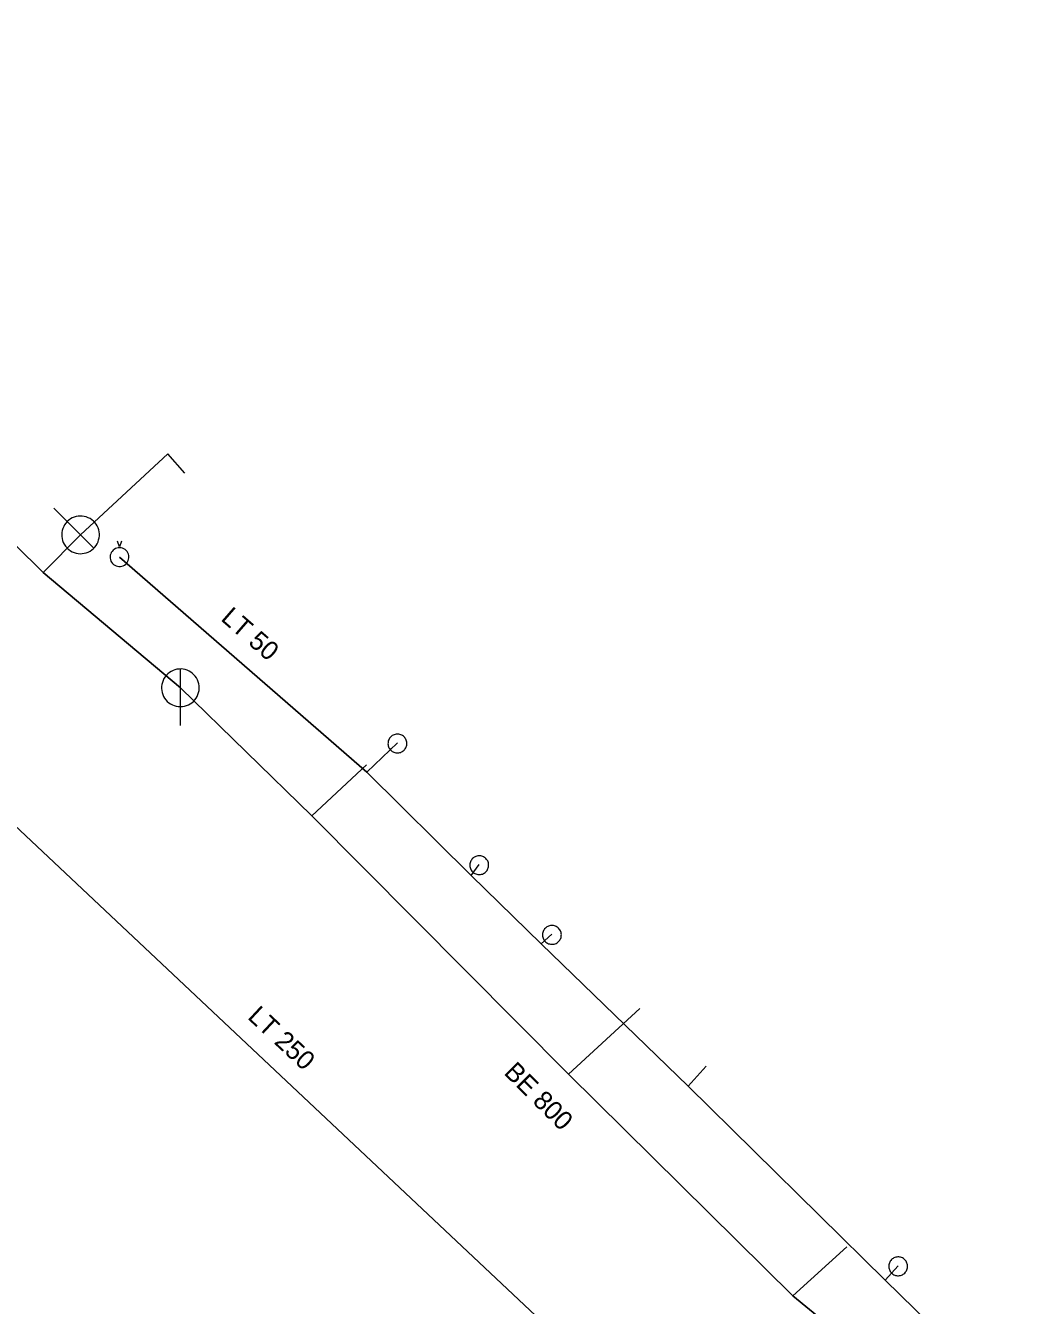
# Model space of a CAD drawing. Extents: x -807203 to -805207, y -993656 to -992505.
# Drawn here: x -806024 to -805970.4, y -993281.2 to -993213.2 of the extents above; entities that cross this region are included whole.
import ezdxf

# ---------------------------------------------------------------- set-up
doc = ezdxf.new("R2010")
doc.units = 0
doc.header["$LTSCALE"] = 0.4
for name, color, linetype, lineweight in [('1', 7, 'Continuous', 13), ('11', 7, 'Continuous', 13), ('13', 7, 'Continuous', 13), ('14', 7, 'Continuous', 25), ('17', 7, 'Continuous', 25), ('22', 7, 'Continuous', 13), ('23', 7, 'Continuous', 13)]:
    doc.layers.add(name, color=color, linetype=linetype, lineweight=lineweight)

msp = doc.modelspace()

# ---------------------------------------------------------------- linework, layer by layer
at = {"layer": '11'}
for p, q in [((-806021.12, -993240.27), (-806023.109, -993242.259)), ((-806005.943, -993252.482), (-806008.844, -993255.179)), ((-805991.421, -993265.414), (-805995.221, -993268.897)), ((-805980.442, -993278.079), (-805983.297, -993280.672))]:
    msp.add_line(p, q, dxfattribs=at)
msp.add_lwpolyline([(-806015.584, -993236.985), (-806016.482, -993235.959), (-806021.12, -993240.27)], dxfattribs=at)
at = {"layer": '13'}
for p, q in [((-806005.914, -993252.87), (-806004.298, -993251.316)), ((-806000.375, -993258.351), (-805999.953, -993257.777)), ((-805996.668, -993261.975), (-805996.094, -993261.478)), ((-805988.86, -993269.541), (-805987.907, -993268.484)), ((-805978.403, -993279.84), (-805977.714, -993279.075))]:
    msp.add_line(p, q, dxfattribs=at)
at = {"layer": '14'}
for points in [[(-806052.51, -993213.23), (-806023.109, -993242.259), (-806015.82, -993248.39)], [(-806015.82, -993248.39), (-806008.844, -993255.179), (-805995.221, -993268.897), (-805983.297, -993280.672), (-805980.85, -993282.69)]]:
    msp.add_lwpolyline(points, dxfattribs=at)
at = {"layer": '17'}
for points in [[(-805970.428, -993287.685), (-805972.109, -993286.008), (-805978.403, -993279.84), (-805988.86, -993269.541), (-805996.668, -993261.975), (-806000.375, -993258.351), (-806005.914, -993252.87), (-806019.053, -993241.45)], [(-805980.27, -993297.811), (-805996.344, -993282.298), (-806025.237, -993255.101)]]:
    msp.add_lwpolyline(points, dxfattribs=at)
at = {"layer": '22'}
for p, q in [((-806022.534, -993238.855), (-806020.413, -993240.976)), ((-806015.82, -993250.39), (-806015.819, -993247.39))]:
    msp.add_line(p, q, dxfattribs=at)
for points in [[(-806021.827, -993240.976), (-806021.746, -993241.049), (-806021.657, -993241.113), (-806021.561, -993241.166), (-806021.461, -993241.21), (-806021.356, -993241.241), (-806021.248, -993241.261), (-806021.138, -993241.269), (-806021.03, -993241.265), (-806020.921, -993241.249), (-806020.815, -993241.222), (-806020.713, -993241.183), (-806020.615, -993241.132), (-806020.524, -993241.072), (-806020.44, -993241.002), (-806020.363, -993240.923), (-806020.297, -993240.836), (-806020.239, -993240.743), (-806020.192, -993240.644), (-806020.158, -993240.54), (-806020.133, -993240.434), (-806020.121, -993240.325), (-806020.121, -993240.216), (-806020.133, -993240.106), (-806020.157, -993239.999), (-806020.192, -993239.896), (-806020.239, -993239.797), (-806020.296, -993239.703), (-806020.362, -993239.617), (-806020.439, -993239.537), (-806020.523, -993239.467), (-806020.613, -993239.407), (-806020.711, -993239.357), (-806020.813, -993239.317), (-806020.919, -993239.289), (-806021.028, -993239.274), (-806021.137, -993239.269), (-806021.246, -993239.277), (-806021.354, -993239.297), (-806021.458, -993239.328), (-806021.559, -993239.371), (-806021.655, -993239.424), (-806021.744, -993239.488), (-806021.826, -993239.561), (-806021.899, -993239.642), (-806021.963, -993239.732), (-806022.016, -993239.826), (-806022.06, -993239.927), (-806022.091, -993240.033), (-806022.111, -993240.14), (-806022.12, -993240.249), (-806022.116, -993240.359), (-806022.1, -993240.467), (-806022.073, -993240.573), (-806022.034, -993240.675), (-806021.984, -993240.772), (-806021.923, -993240.864), (-806021.853, -993240.948)], [(-806014.82, -993248.39), (-806014.825, -993248.281), (-806014.843, -993248.173), (-806014.873, -993248.067), (-806014.913, -993247.966), (-806014.965, -993247.869), (-806015.027, -993247.779), (-806015.099, -993247.696), (-806015.179, -993247.622), (-806015.267, -993247.556), (-806015.361, -993247.501), (-806015.461, -993247.456), (-806015.566, -993247.423), (-806015.673, -993247.401), (-806015.782, -993247.391), (-806015.892, -993247.393), (-806016, -993247.407), (-806016.107, -993247.432), (-806016.21, -993247.469), (-806016.308, -993247.518), (-806016.4, -993247.576), (-806016.486, -993247.645), (-806016.563, -993247.722), (-806016.632, -993247.808), (-806016.691, -993247.9), (-806016.739, -993247.998), (-806016.776, -993248.101), (-806016.802, -993248.208), (-806016.816, -993248.316), (-806016.819, -993248.426), (-806016.809, -993248.535), (-806016.788, -993248.642), (-806016.754, -993248.746), (-806016.71, -993248.846), (-806016.655, -993248.941), (-806016.589, -993249.029), (-806016.515, -993249.109), (-806016.432, -993249.181), (-806016.342, -993249.243), (-806016.246, -993249.295), (-806016.144, -993249.336), (-806016.039, -993249.366), (-806015.931, -993249.384), (-806015.821, -993249.39), (-806015.712, -993249.384), (-806015.604, -993249.366), (-806015.499, -993249.337), (-806015.397, -993249.296), (-806015.3, -993249.244), (-806015.21, -993249.182), (-806015.127, -993249.111), (-806015.052, -993249.031), (-806014.987, -993248.943), (-806014.931, -993248.849), (-806014.887, -993248.749), (-806014.853, -993248.645), (-806014.831, -993248.537), (-806014.821, -993248.428)]]:
    msp.add_lwpolyline(points, close=True, dxfattribs=at)
at = {"layer": '23'}
msp.add_lwpolyline([(-806018.554, -993241.45), (-806018.56, -993241.373), (-806018.578, -993241.298), (-806018.607, -993241.226), (-806018.647, -993241.16), (-806018.697, -993241.101), (-806018.755, -993241.05), (-806018.82, -993241.009), (-806018.891, -993240.979), (-806018.966, -993240.96), (-806019.043, -993240.952), (-806019.12, -993240.957), (-806019.196, -993240.973), (-806019.268, -993241.001), (-806019.334, -993241.04), (-806019.394, -993241.089), (-806019.446, -993241.146), (-806019.489, -993241.211), (-806019.52, -993241.281), (-806019.541, -993241.355), (-806019.55, -993241.432), (-806019.547, -993241.509), (-806019.532, -993241.585), (-806019.505, -993241.658), (-806019.468, -993241.725), (-806019.42, -993241.786), (-806019.364, -993241.839), (-806019.3, -993241.882), (-806019.23, -993241.915), (-806019.156, -993241.937), (-806019.08, -993241.947), (-806019.002, -993241.945), (-806018.926, -993241.931), (-806018.853, -993241.906), (-806018.785, -993241.87), (-806018.724, -993241.823), (-806018.67, -993241.768), (-806018.625, -993241.705), (-806018.591, -993241.636), (-806018.568, -993241.562), (-806018.556, -993241.486)], close=True, dxfattribs=at)
for points in [[(-806018.945, -993240.602), (-806019.048, -993240.913), (-806019.151, -993240.602)], [(-806003.942, -993250.997), (-806003.981, -993250.961), (-806004.023, -993250.93), (-806004.068, -993250.905), (-806004.116, -993250.883), (-806004.165, -993250.866), (-806004.217, -993250.856), (-806004.268, -993250.85), (-806004.32, -993250.849), (-806004.372, -993250.854), (-806004.424, -993250.864), (-806004.474, -993250.88), (-806004.523, -993250.901), (-806004.568, -993250.927), (-806004.609, -993250.957), (-806004.649, -993250.991), (-806004.685, -993251.031), (-806004.715, -993251.072), (-806004.742, -993251.118), (-806004.764, -993251.164), (-806004.781, -993251.214), (-806004.791, -993251.267), (-806004.797, -993251.318), (-806004.798, -993251.371), (-806004.794, -993251.423), (-806004.783, -993251.473), (-806004.766, -993251.524), (-806004.746, -993251.571), (-806004.72, -993251.617), (-806004.688, -993251.659), (-806004.655, -993251.699), (-806004.616, -993251.734), (-806004.574, -993251.765), (-806004.528, -993251.792), (-806004.481, -993251.814), (-806004.432, -993251.829), (-806004.381, -993251.84), (-806004.329, -993251.847), (-806004.276, -993251.847), (-806004.224, -993251.842)], [(-806004.742, -993251.118), (-806004.764, -993251.164), (-806004.781, -993251.214), (-806004.791, -993251.267), (-806004.797, -993251.318), (-806004.798, -993251.371), (-806004.794, -993251.423), (-806004.783, -993251.473), (-806004.766, -993251.524), (-806004.746, -993251.571), (-806004.72, -993251.617), (-806004.688, -993251.659), (-806004.655, -993251.699), (-806004.616, -993251.734), (-806004.574, -993251.765), (-806004.528, -993251.792), (-806004.481, -993251.814), (-806004.432, -993251.829), (-806004.381, -993251.84), (-806004.329, -993251.847), (-806004.276, -993251.847), (-806004.224, -993251.842), (-806004.173, -993251.832), (-806004.123, -993251.816), (-806004.075, -993251.796), (-806004.029, -993251.769), (-806003.988, -993251.738), (-806003.948, -993251.704), (-806003.913, -993251.666), (-806003.882, -993251.624), (-806003.855, -993251.578), (-806003.834, -993251.531), (-806003.817, -993251.481), (-806003.805, -993251.431), (-806003.8, -993251.378), (-806003.799, -993251.326), (-806003.804, -993251.274), (-806003.814, -993251.222), (-806003.83, -993251.172), (-806003.851, -993251.124)], [(-806004.224, -993251.842), (-806004.173, -993251.832), (-806004.123, -993251.816), (-806004.075, -993251.796), (-806004.029, -993251.769), (-806003.988, -993251.738), (-806003.948, -993251.704), (-806003.913, -993251.666), (-806003.882, -993251.624), (-806003.855, -993251.578), (-806003.834, -993251.531), (-806003.817, -993251.481), (-806003.805, -993251.431), (-806003.8, -993251.378), (-806003.799, -993251.326), (-806003.804, -993251.274), (-806003.814, -993251.222), (-806003.83, -993251.172), (-806003.851, -993251.124), (-806003.878, -993251.079), (-806003.908, -993251.037), (-806003.942, -993250.997), (-806003.981, -993250.961), (-806004.023, -993250.93), (-806004.068, -993250.905), (-806004.116, -993250.883), (-806004.165, -993250.866), (-806004.217, -993250.856), (-806004.268, -993250.85), (-806004.32, -993250.849), (-806004.372, -993250.854), (-806004.424, -993250.864), (-806004.474, -993250.88), (-806004.523, -993250.901), (-806004.568, -993250.927), (-806004.609, -993250.957), (-806004.649, -993250.991), (-806004.685, -993251.031), (-806004.715, -993251.072), (-806004.742, -993251.118)], [(-806003.851, -993251.124), (-806003.878, -993251.079), (-806003.908, -993251.037), (-806003.942, -993250.997)], [(-805999.597, -993257.458), (-805999.636, -993257.422), (-805999.678, -993257.391), (-805999.723, -993257.366), (-805999.771, -993257.344), (-805999.82, -993257.327), (-805999.872, -993257.317), (-805999.923, -993257.311), (-805999.975, -993257.31), (-806000.027, -993257.315), (-806000.079, -993257.325), (-806000.129, -993257.341), (-806000.178, -993257.362), (-806000.223, -993257.388), (-806000.264, -993257.418), (-806000.304, -993257.452), (-806000.34, -993257.492), (-806000.37, -993257.533), (-806000.397, -993257.579), (-806000.419, -993257.625), (-806000.436, -993257.675), (-806000.446, -993257.728), (-806000.452, -993257.779), (-806000.453, -993257.832), (-806000.449, -993257.884), (-806000.438, -993257.934), (-806000.421, -993257.985), (-806000.401, -993258.032), (-806000.375, -993258.078), (-806000.343, -993258.12), (-806000.31, -993258.16), (-806000.271, -993258.195), (-806000.229, -993258.226), (-806000.183, -993258.253), (-806000.136, -993258.275), (-806000.087, -993258.29), (-806000.036, -993258.301), (-805999.984, -993258.308), (-805999.931, -993258.308), (-805999.879, -993258.303)], [(-805999.879, -993258.303), (-805999.828, -993258.293), (-805999.778, -993258.277), (-805999.73, -993258.257), (-805999.684, -993258.23), (-805999.643, -993258.199), (-805999.603, -993258.165), (-805999.568, -993258.127), (-805999.537, -993258.085), (-805999.51, -993258.039), (-805999.489, -993257.992), (-805999.472, -993257.942), (-805999.46, -993257.892), (-805999.455, -993257.839), (-805999.454, -993257.787), (-805999.459, -993257.735), (-805999.469, -993257.683), (-805999.485, -993257.633), (-805999.506, -993257.585), (-805999.533, -993257.54), (-805999.563, -993257.498), (-805999.597, -993257.458), (-805999.636, -993257.422), (-805999.678, -993257.391), (-805999.723, -993257.366), (-805999.771, -993257.344), (-805999.82, -993257.327), (-805999.872, -993257.317), (-805999.923, -993257.311), (-805999.975, -993257.31), (-806000.027, -993257.315), (-806000.079, -993257.325), (-806000.129, -993257.341), (-806000.178, -993257.362), (-806000.223, -993257.388), (-806000.264, -993257.418), (-806000.304, -993257.452), (-806000.34, -993257.492), (-806000.37, -993257.533), (-806000.397, -993257.579)], [(-806000.397, -993257.579), (-806000.419, -993257.625), (-806000.436, -993257.675), (-806000.446, -993257.728), (-806000.452, -993257.779), (-806000.453, -993257.832), (-806000.449, -993257.884), (-806000.438, -993257.934), (-806000.421, -993257.985), (-806000.401, -993258.032), (-806000.375, -993258.078), (-806000.343, -993258.12), (-806000.31, -993258.16), (-806000.271, -993258.195), (-806000.229, -993258.226), (-806000.183, -993258.253), (-806000.136, -993258.275), (-806000.087, -993258.29), (-806000.036, -993258.301), (-805999.984, -993258.308), (-805999.931, -993258.308), (-805999.879, -993258.303), (-805999.828, -993258.293), (-805999.778, -993258.277), (-805999.73, -993258.257), (-805999.684, -993258.23), (-805999.643, -993258.199), (-805999.603, -993258.165), (-805999.568, -993258.127), (-805999.537, -993258.085), (-805999.51, -993258.039), (-805999.489, -993257.992), (-805999.472, -993257.942), (-805999.46, -993257.892), (-805999.455, -993257.839), (-805999.454, -993257.787), (-805999.459, -993257.735), (-805999.469, -993257.683), (-805999.485, -993257.633), (-805999.506, -993257.585)], [(-805999.506, -993257.585), (-805999.533, -993257.54), (-805999.563, -993257.498), (-805999.597, -993257.458)], [(-805995.738, -993261.159), (-805995.777, -993261.123), (-805995.819, -993261.092), (-805995.864, -993261.067), (-805995.912, -993261.045), (-805995.961, -993261.028), (-805996.013, -993261.018), (-805996.064, -993261.012), (-805996.116, -993261.011), (-805996.168, -993261.016), (-805996.22, -993261.026), (-805996.27, -993261.042), (-805996.319, -993261.063), (-805996.364, -993261.089), (-805996.405, -993261.119), (-805996.445, -993261.153), (-805996.481, -993261.193), (-805996.511, -993261.234), (-805996.538, -993261.28), (-805996.56, -993261.326), (-805996.577, -993261.376), (-805996.587, -993261.429), (-805996.593, -993261.48), (-805996.594, -993261.533), (-805996.59, -993261.585), (-805996.579, -993261.635), (-805996.562, -993261.686), (-805996.542, -993261.733), (-805996.516, -993261.779), (-805996.484, -993261.821), (-805996.451, -993261.861), (-805996.412, -993261.896), (-805996.37, -993261.927), (-805996.324, -993261.954), (-805996.277, -993261.976), (-805996.228, -993261.991), (-805996.177, -993262.002), (-805996.125, -993262.009), (-805996.072, -993262.009), (-805996.02, -993262.004)], [(-805996.538, -993261.28), (-805996.56, -993261.326), (-805996.577, -993261.376), (-805996.587, -993261.429), (-805996.593, -993261.48), (-805996.594, -993261.533), (-805996.59, -993261.585), (-805996.579, -993261.635), (-805996.562, -993261.686), (-805996.542, -993261.733), (-805996.516, -993261.779), (-805996.484, -993261.821), (-805996.451, -993261.861), (-805996.412, -993261.896), (-805996.37, -993261.927), (-805996.324, -993261.954), (-805996.277, -993261.976), (-805996.228, -993261.991), (-805996.177, -993262.002), (-805996.125, -993262.009), (-805996.072, -993262.009), (-805996.02, -993262.004), (-805995.969, -993261.994), (-805995.919, -993261.978), (-805995.871, -993261.958), (-805995.825, -993261.931), (-805995.784, -993261.9), (-805995.744, -993261.866), (-805995.709, -993261.828), (-805995.678, -993261.786), (-805995.651, -993261.74), (-805995.63, -993261.693), (-805995.613, -993261.643), (-805995.601, -993261.593), (-805995.596, -993261.54), (-805995.595, -993261.488), (-805995.6, -993261.436), (-805995.61, -993261.384), (-805995.626, -993261.334), (-805995.647, -993261.286)], [(-805996.02, -993262.004), (-805995.969, -993261.994), (-805995.919, -993261.978), (-805995.871, -993261.958), (-805995.825, -993261.931), (-805995.784, -993261.9), (-805995.744, -993261.866), (-805995.709, -993261.828), (-805995.678, -993261.786), (-805995.651, -993261.74), (-805995.63, -993261.693), (-805995.613, -993261.643), (-805995.601, -993261.593), (-805995.596, -993261.54), (-805995.595, -993261.488), (-805995.6, -993261.436), (-805995.61, -993261.384), (-805995.626, -993261.334), (-805995.647, -993261.286), (-805995.674, -993261.241), (-805995.704, -993261.199), (-805995.738, -993261.159), (-805995.777, -993261.123), (-805995.819, -993261.092), (-805995.864, -993261.067), (-805995.912, -993261.045), (-805995.961, -993261.028), (-805996.013, -993261.018), (-805996.064, -993261.012), (-805996.116, -993261.011), (-805996.168, -993261.016), (-805996.22, -993261.026), (-805996.27, -993261.042), (-805996.319, -993261.063), (-805996.364, -993261.089), (-805996.405, -993261.119), (-805996.445, -993261.153), (-805996.481, -993261.193), (-805996.511, -993261.234), (-805996.538, -993261.28)], [(-805995.647, -993261.286), (-805995.674, -993261.241), (-805995.704, -993261.199), (-805995.738, -993261.159)], [(-805977.358, -993278.756), (-805977.397, -993278.72), (-805977.439, -993278.689), (-805977.484, -993278.664), (-805977.532, -993278.642), (-805977.581, -993278.625), (-805977.633, -993278.615), (-805977.684, -993278.609), (-805977.736, -993278.608), (-805977.788, -993278.613), (-805977.84, -993278.623), (-805977.89, -993278.639), (-805977.939, -993278.66), (-805977.984, -993278.686), (-805978.025, -993278.716), (-805978.065, -993278.75), (-805978.101, -993278.79), (-805978.131, -993278.831), (-805978.158, -993278.877), (-805978.18, -993278.923), (-805978.197, -993278.973), (-805978.207, -993279.026), (-805978.213, -993279.077), (-805978.214, -993279.13), (-805978.21, -993279.182), (-805978.199, -993279.232), (-805978.182, -993279.283), (-805978.162, -993279.33), (-805978.136, -993279.376), (-805978.104, -993279.418), (-805978.071, -993279.458), (-805978.032, -993279.493), (-805977.99, -993279.524), (-805977.944, -993279.551), (-805977.897, -993279.573), (-805977.848, -993279.588), (-805977.797, -993279.599), (-805977.745, -993279.606), (-805977.692, -993279.606), (-805977.64, -993279.601)], [(-805978.158, -993278.877), (-805978.18, -993278.923), (-805978.197, -993278.973), (-805978.207, -993279.026), (-805978.213, -993279.077), (-805978.214, -993279.13), (-805978.21, -993279.182), (-805978.199, -993279.232), (-805978.182, -993279.283), (-805978.162, -993279.33), (-805978.136, -993279.376), (-805978.104, -993279.418), (-805978.071, -993279.458), (-805978.032, -993279.493), (-805977.99, -993279.524), (-805977.944, -993279.551), (-805977.897, -993279.573), (-805977.848, -993279.588), (-805977.797, -993279.599), (-805977.745, -993279.606), (-805977.692, -993279.606), (-805977.64, -993279.601), (-805977.589, -993279.591), (-805977.539, -993279.575), (-805977.491, -993279.555), (-805977.445, -993279.528), (-805977.404, -993279.497), (-805977.364, -993279.463), (-805977.329, -993279.425), (-805977.298, -993279.383), (-805977.271, -993279.337), (-805977.25, -993279.29), (-805977.233, -993279.24), (-805977.221, -993279.19), (-805977.216, -993279.137), (-805977.215, -993279.085), (-805977.22, -993279.033), (-805977.23, -993278.981), (-805977.246, -993278.931), (-805977.267, -993278.883)], [(-805977.64, -993279.601), (-805977.589, -993279.591), (-805977.539, -993279.575), (-805977.491, -993279.555), (-805977.445, -993279.528), (-805977.404, -993279.497), (-805977.364, -993279.463), (-805977.329, -993279.425), (-805977.298, -993279.383), (-805977.271, -993279.337), (-805977.25, -993279.29), (-805977.233, -993279.24), (-805977.221, -993279.19), (-805977.216, -993279.137), (-805977.215, -993279.085), (-805977.22, -993279.033), (-805977.23, -993278.981), (-805977.246, -993278.931), (-805977.267, -993278.883), (-805977.294, -993278.838), (-805977.324, -993278.796), (-805977.358, -993278.756), (-805977.397, -993278.72), (-805977.439, -993278.689), (-805977.484, -993278.664), (-805977.532, -993278.642), (-805977.581, -993278.625), (-805977.633, -993278.615), (-805977.684, -993278.609), (-805977.736, -993278.608), (-805977.788, -993278.613), (-805977.84, -993278.623), (-805977.89, -993278.639), (-805977.939, -993278.66), (-805977.984, -993278.686), (-805978.025, -993278.716), (-805978.065, -993278.75), (-805978.101, -993278.79), (-805978.131, -993278.831), (-805978.158, -993278.877)], [(-805977.267, -993278.883), (-805977.294, -993278.838), (-805977.324, -993278.796), (-805977.358, -993278.756)]]:
    msp.add_lwpolyline(points, dxfattribs=at)

# ---------------------------------------------------------------- texts
at = {"layer": '1'}
for s, rotation, p in [('LT 50 ', 319, (-806013.723, -993244.776)), ('LT 250', 317, (-806012.3, -993265.925)), ('BE 800', 315, (-805998.694, -993268.865))]:
    msp.add_text(s, height=1, rotation=rotation, dxfattribs=at).set_placement(p)

doc.saveas('drawing.dxf')
